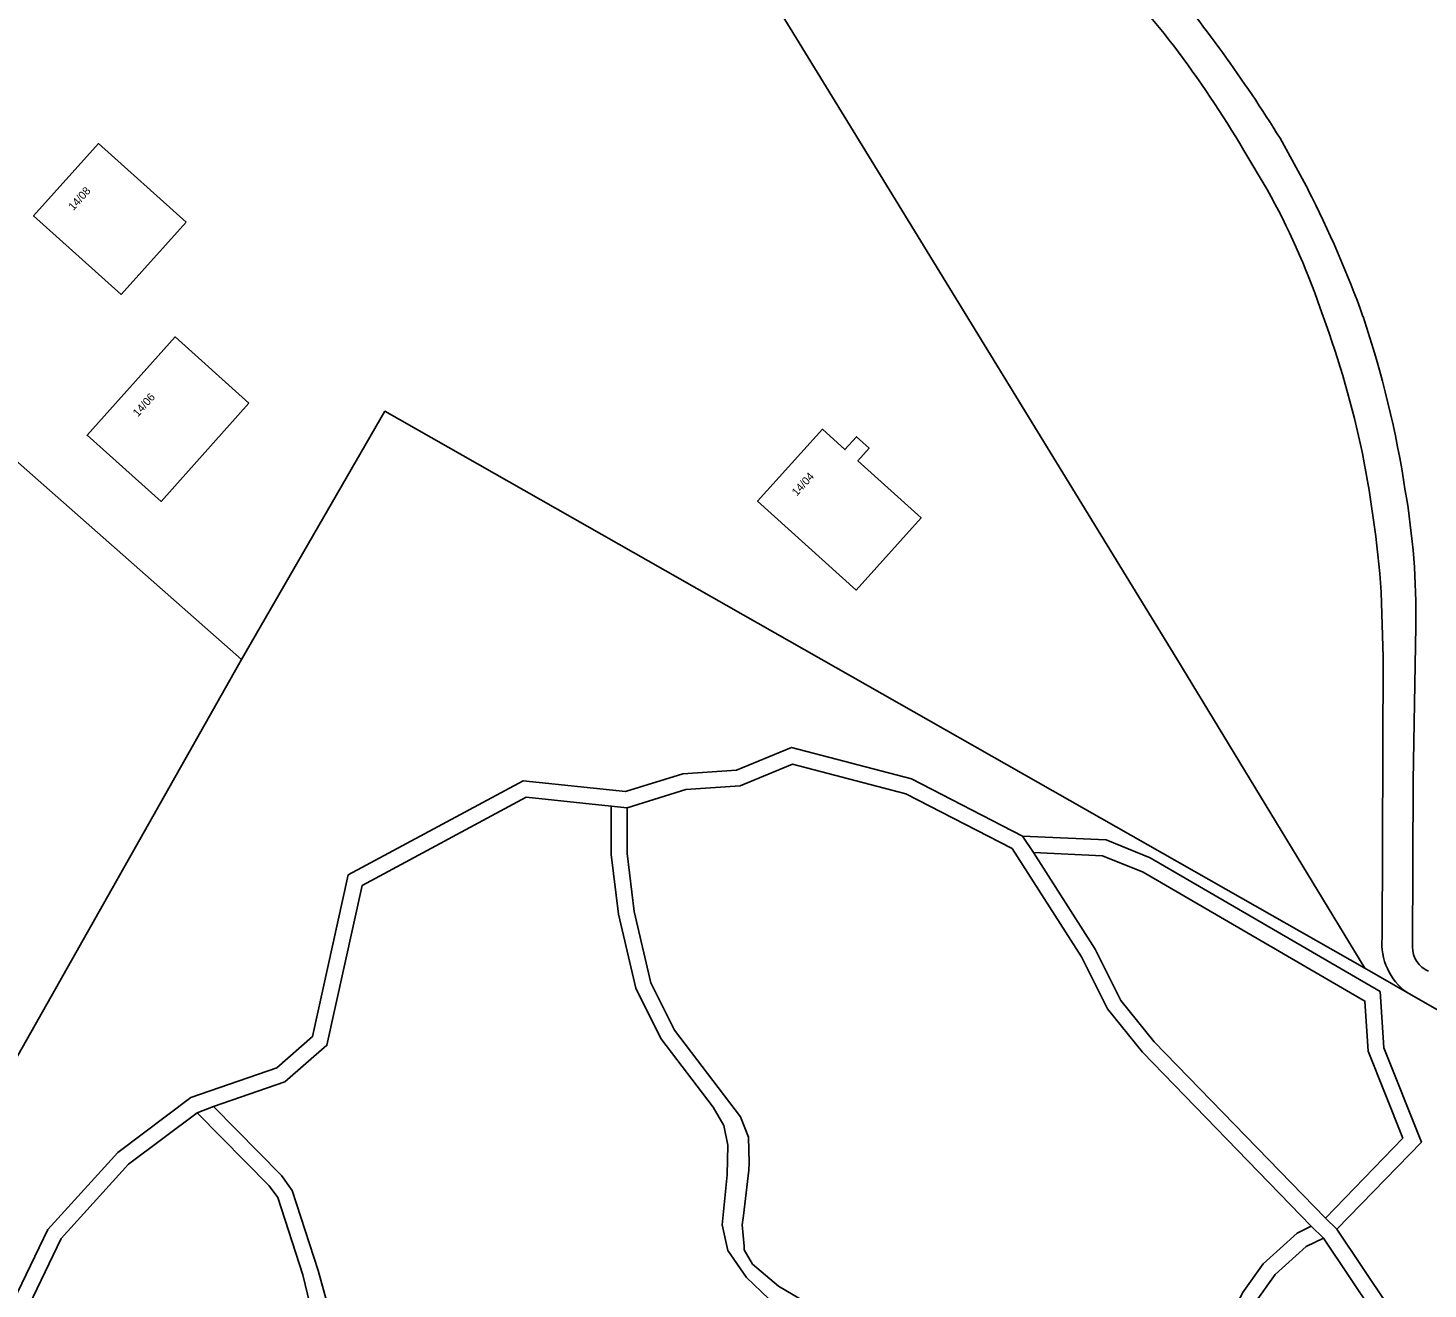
# Model space of a CAD drawing. Extents: x 157132 to 159279, y 384991 to 386650.
# Drawn here: x 157894.6 to 158070.6, y 385861.9 to 386020.3 of the extents above; entities that cross this region are included whole.
import ezdxf

# ---------------------------------------------------------------- set-up
doc = ezdxf.new("R2010")
doc.units = 0
for name, color, linetype in [('IMGEO_Gemengd_bos', 7, 'Continuous'), ('IMGEO_Groenvoorziening', 7, 'Continuous'), ('IMGEO_Hek', 7, 'Continuous'), ('IMGEO_Loofbos', 7, 'Continuous'), ('IMGEO_Pand', 7, 'Continuous'), ('IMGEO_Pand_nummerreeks', 7, 'Continuous'), ('IMGEO_Voetpad_halfverhard', 7, 'Continuous')]:
    doc.layers.add(name, color=color, linetype=linetype)

msp = doc.modelspace()

# ---------------------------------------------------------------- linework, layer by layer
at = {"layer": 'IMGEO_Gemengd_bos'}
for points in [[(158001.54, 386050.04), (158000, 386050.87), (157996.46, 386052.93), (157993.21, 386055.25), (157983.96, 386062.91), (157976.98, 386068.09), (157969.25, 386073.06), (157964.03, 386076.09), (157956.78, 386079.93), (157925.82, 386094.62), (157923.9, 386092.49), (157974.24, 386046.68), (158002.86, 386000), (158038.99, 385941.05), (158062.63, 385902.16), (158067.95, 385899.1)], [(158050.38, 386000), (158047.44, 386004.93)], [(158064.82, 385905.95), (158064.94, 385941.26), (158064.71, 385949.43)]]:
    msp.add_lwpolyline(points, dxfattribs=at)
for centre, radius, start, end in [((157938.23, 385939.58), 127.43, 38.0162, 45.0575), ((157922.7, 385930.71), 145.15, 30.7523, 37.0015), ((157967.49, 385954.01), 94.79, 19.1586, 29.0254), ((157934.8, 385939.53), 130.45, 12.5947, 20.4545), ((157914.48, 385937.91), 150.67, 4.3831, 11.5094), ((158072.36, 385905.26), 7.57, 174.8119, 234.4225)]:
    msp.add_arc(centre, radius, start, end, dxfattribs=at)
at = {"layer": 'IMGEO_Groenvoorziening'}
for points in [[(158062.63, 385902.16), (158038.99, 385941.05), (158002.86, 386000), (157974.24, 386046.68), (157923.9, 386092.49)], [(157840.47, 386012.79), (157854.58, 386000), (157882.35, 385975.36), (157921.45, 385940.96)], [(157750.58, 385919.79), (157748.18, 385918.41), (157746.48, 385917.53), (157748.39, 385916.43), (157748.86, 385916.17), (157748.99, 385916.39), (157749.19, 385916.71), (157801.31, 385887.35), (157869.06, 385848.74), (157892.38, 385889.57), (157921.45, 385940.96), (157882.35, 385975.36)], [(158123.93, 385866.99), (158105.5, 385877.57), (158078.34, 385893.15), (158067.95, 385899.1), (158062.63, 385902.16), (157939.45, 385972.14), (157921.45, 385940.96), (157892.38, 385889.57)], [(157921.45, 385940.96), (157939.45, 385972.14)], [(157939.45, 385972.14), (158062.63, 385902.16)], [(157888.34, 385851.23), (157897.07, 385869.34), (157905.88, 385879.01), (157915.07, 385885.91), (157925.86, 385889.66), (157930.36, 385893.56), (157934.85, 385913.88), (157956.82, 385925.7), (157969.71, 385924.35), (157976.91, 385926.6), (157983.66, 385927.05), (157990.55, 385929.9), (158005.67, 385925.97), (158019.61, 385918.77), (158030.11, 385918.28), (158035.65, 385916.03), (158064.59, 385899.23), (158065.04, 385892.17), (158069.76, 385880.32), (158059.11, 385869.37), (158065.56, 385859.72)]]:
    msp.add_lwpolyline(points, dxfattribs=at)
for points in [[(157914.46, 385995.9), (157906.31, 385986.82), (157895.29, 385996.7), (157903.44, 386005.78)], [(157922.37, 385973.18), (157911.31, 385960.82), (157902.02, 385969.13), (157913.08, 385981.49)], [(157986.3, 385960.85), (157994.45, 385969.89), (157997.29, 385967.33), (157998.74, 385968.95), (158000.33, 385967.51), (157998.91, 385965.93), (158006.87, 385958.75), (157998.69, 385949.68)], [(158067.42, 385880.79), (158063.06, 385891.73), (158062.66, 385898.03), (158034.77, 385914.23), (158029.67, 385916.3), (158021, 385916.7), (158028.75, 385904.56), (158031.99, 385898.12), (158036.18, 385892.93), (158057.68, 385870.76)]]:
    msp.add_lwpolyline(points, close=True, dxfattribs=at)
at = {"layer": 'IMGEO_Hek'}
for points in [[(157840.47, 386012.79), (157854.58, 386000), (157882.35, 385975.36), (157921.45, 385940.96)], [(157921.45, 385940.96), (157892.38, 385889.57), (157869.06, 385848.74)]]:
    msp.add_lwpolyline(points, dxfattribs=at)
at = {"layer": 'IMGEO_Loofbos'}
for points in [[(158051.98, 386006.46), (158055.5, 386000)], [(158069.05, 385945.1), (158068.72, 385925.76), (158068.62, 385904.84)], [(158047.25, 385861.36), (158049.88, 385865.02), (158054.13, 385868.86), (158055.9, 385869.73), (158034.68, 385891.6), (158030.3, 385897.04), (158027.01, 385903.57), (158018.32, 385917.19), (158004.95, 385924.09), (157990.7, 385927.8), (157984.12, 385925.08), (157977.28, 385924.62), (157969.92, 385922.32), (157969.92, 385916.57), (157970.8, 385909.29), (157972.9, 385900.32), (157975.85, 385894.38), (157984.17, 385883.47), (157985.18, 385880.91), (157985.24, 385877.7), (157985.22, 385876.8), (157984.52, 385871.08), (157984.38, 385869.9), (157984.6, 385867.25), (157984.64, 385866.77), (157985.66, 385864.98), (157988.93, 385862.2), (157992.41, 385860.15)], [(157981.86, 385869.93), (157982.48, 385876.19), (157982.55, 385879.92), (157982.05, 385882.41), (157980.71, 385884.71), (157974.14, 385893.32), (157971.01, 385899.64), (157968.82, 385908.94), (157967.92, 385916.45), (157967.92, 385922.53), (157957.23, 385923.65), (157936.61, 385912.56), (157932.17, 385892.48), (157926.88, 385887.9), (157917.89, 385884.78), (157926.45, 385876.12), (157927.8, 385874.24), (157931.07, 385864.18), (157933.75, 385854.48), (157934.2, 385854.58), (157947.36, 385857.71)], [(157931.49, 385853.9), (157929.15, 385863.64), (157925.99, 385873.33), (157924.92, 385874.83), (157915.85, 385884), (157907.24, 385877.52), (157898.75, 385868.21), (157890.21, 385850.5), (157886.5, 385838.07), (157886.42, 385837.79), (157887.04, 385837.44), (157891.1, 385835.11), (157891.04, 385835), (157892.69, 385834.05), (157895.76, 385832.78), (157900.53, 385830.8), (157902.59, 385830.53), (157907.03, 385832.78), (157913.38, 385839.94), (157921.99, 385847.5), (157928.85, 385852.59)], [(158029.03, 385832.69), (158029.57, 385837.13), (158030.11, 385838.47), (158030.2, 385838.69), (158023.06, 385841.22), (158018.37, 385843.43), (158003.65, 385854.05), (158000.38, 385855.79), (157996.62, 385857.01), (157991.64, 385858.28), (157987.71, 385860.6), (157984.91, 385863.3), (157982.56, 385866.68), (157981.86, 385869.93)], [(158057.77, 385805.8), (158067.76, 385806.38), (158071.55, 385812.97), (158071.89, 385812.84), (158073.95, 385816.38), (158073.04, 385816.9), (158082.29, 385833.08), (158076.62, 385836.7), (158074.7, 385838.87), (158070.54, 385847.09), (158069.74, 385846.69), (158063.82, 385858.72), (158057.45, 385868.26), (158055.26, 385867.19), (158051.38, 385863.68), (158048.98, 385860.33), (158046.32, 385854.85), (158044.79, 385849.35), (158044.42, 385828.86), (158041.42, 385823.92), (158034.43, 385816.48)]]:
    msp.add_lwpolyline(points, dxfattribs=at)
for centre, radius, start, end in [((157904.96, 385915.58), 172.84, 31.7213, 40.2852), ((157933.6, 385937.69), 136.9, 19.7925, 27.0745), ((157939.5, 385942.65), 129.7, 8.6355, 18.6126), ((157977.16, 385946.5), 91.91, 359.1234, 9.7878), ((158071.98, 385904.87), 3.36, 180.5005, 246.9314)]:
    msp.add_arc(centre, radius, start, end, dxfattribs=at)
at = {"layer": 'IMGEO_Pand'}
for points in [[(157914.46, 385995.9), (157903.44, 386005.78), (157895.29, 385996.7), (157906.31, 385986.82)], [(157922.37, 385973.18), (157913.08, 385981.49), (157902.02, 385969.13), (157911.31, 385960.82)], [(157998.69, 385949.68), (158006.87, 385958.75), (157998.91, 385965.93), (158000.33, 385967.51), (157998.74, 385968.95), (157997.29, 385967.33), (157994.45, 385969.89), (157986.3, 385960.85)]]:
    msp.add_lwpolyline(points, close=True, dxfattribs=at)
at = {"layer": 'IMGEO_Voetpad_halfverhard'}
for points in [[(158055.5, 386000), (158051.98, 386006.46)], [(158047.44, 386004.93), (158050.38, 386000)], [(158064.71, 385949.43), (158064.94, 385941.26), (158064.82, 385905.95)], [(158068.62, 385904.84), (158068.72, 385925.76), (158069.05, 385945.1)], [(158065.56, 385859.72), (158059.11, 385869.37), (158057.68, 385870.76), (158036.18, 385892.93), (158031.99, 385898.12), (158028.75, 385904.56), (158021, 385916.7), (158019.61, 385918.77), (158005.67, 385925.97), (157990.55, 385929.9), (157983.66, 385927.05), (157976.91, 385926.6), (157969.71, 385924.35), (157956.82, 385925.7), (157934.85, 385913.88), (157930.36, 385893.56), (157925.86, 385889.66), (157915.07, 385885.91), (157905.88, 385879.01), (157897.07, 385869.34), (157888.34, 385851.23)], [(157890.21, 385850.5), (157898.75, 385868.21), (157907.24, 385877.52), (157915.85, 385884), (157917.89, 385884.78), (157926.88, 385887.9), (157932.17, 385892.48), (157936.61, 385912.56), (157957.23, 385923.65), (157967.92, 385922.53), (157969.92, 385922.32), (157977.28, 385924.62), (157984.12, 385925.08), (157990.7, 385927.8), (158004.95, 385924.09), (158018.32, 385917.19), (158027.01, 385903.57), (158030.3, 385897.04), (158034.68, 385891.6), (158055.9, 385869.73), (158057.45, 385868.26), (158063.82, 385858.72)], [(157992.41, 385860.15), (157988.93, 385862.2), (157985.66, 385864.98), (157984.64, 385866.77), (157984.6, 385867.25), (157984.38, 385869.9), (157984.52, 385871.08), (157985.22, 385876.8), (157985.24, 385877.7), (157985.18, 385880.91), (157984.17, 385883.47), (157975.85, 385894.38), (157972.9, 385900.32), (157970.8, 385909.29), (157969.92, 385916.57), (157969.92, 385922.32), (157967.92, 385922.53), (157967.92, 385916.45), (157968.82, 385908.94), (157971.01, 385899.64), (157974.14, 385893.32), (157980.71, 385884.71), (157982.05, 385882.41), (157982.55, 385879.92), (157982.48, 385876.19), (157981.86, 385869.93), (157982.56, 385866.68), (157984.91, 385863.3), (157987.71, 385860.6)], [(158067.95, 385899.1), (158078.34, 385893.15), (158105.5, 385877.57), (158127.43, 385879.53), (158135.4, 385880.01)], [(158044.42, 385828.86), (158044.79, 385849.35), (158046.32, 385854.85), (158048.98, 385860.33), (158051.38, 385863.68), (158055.26, 385867.19), (158057.45, 385868.26), (158055.9, 385869.73), (158054.13, 385868.86), (158049.88, 385865.02), (158047.25, 385861.36), (158044.45, 385855.56), (158042.79, 385849.65), (158042.55, 385836.11), (158042.51, 385834), (158042.43, 385829.44), (158039.82, 385825.14), (158031.75, 385816.56), (158030.24, 385813.95), (158030.4, 385813.05), (158030.45, 385811.56)]]:
    msp.add_lwpolyline(points, dxfattribs=at)
for points in [[(158035.65, 385916.03), (158030.11, 385918.28), (158019.61, 385918.77), (158021, 385916.7), (158029.67, 385916.3), (158034.77, 385914.23), (158062.66, 385898.03), (158063.06, 385891.73), (158067.42, 385880.79), (158057.68, 385870.76), (158059.11, 385869.37), (158069.76, 385880.32), (158065.04, 385892.17), (158064.59, 385899.23)], [(157927.8, 385874.24), (157926.45, 385876.12), (157917.89, 385884.78), (157915.85, 385884), (157924.92, 385874.83), (157925.99, 385873.33), (157929.15, 385863.64), (157931.49, 385853.9), (157932.17, 385854.1), (157932.25, 385854.12), (157933.75, 385854.48), (157931.07, 385864.18)]]:
    msp.add_lwpolyline(points, close=True, dxfattribs=at)
for centre, radius, start, end in [((157938.23, 385939.58), 127.43, 38.0162, 45.0575), ((157904.96, 385915.58), 172.84, 31.7213, 40.2852), ((157922.7, 385930.71), 145.15, 30.7523, 37.0015), ((157967.49, 385954.01), 94.79, 19.1586, 29.0254), ((157933.6, 385937.69), 136.9, 19.7925, 27.0745), ((157934.8, 385939.53), 130.45, 12.5947, 20.4545), ((157939.5, 385942.65), 129.7, 8.6355, 18.6126), ((157914.48, 385937.91), 150.67, 4.3831, 11.5094), ((157977.16, 385946.5), 91.91, 359.1234, 9.7878), ((158072.36, 385905.26), 7.57, 174.8119, 234.4225), ((158071.98, 385904.87), 3.36, 180.5005, 246.9314)]:
    msp.add_arc(centre, radius, start, end, dxfattribs=at)

# ---------------------------------------------------------------- texts
at = {"layer": 'IMGEO_Pand_nummerreeks'}
for s, rotation, p in [('14/08', 48.0086, (157900.3, 385997.3)), ('14/06', 48.2415, (157908.41, 385971.37)), ('14/04', 47.6698, (157991.24, 385961.42))]:
    msp.add_text(s, height=1, rotation=rotation, dxfattribs=at).set_placement(p)

doc.saveas('drawing.dxf')
